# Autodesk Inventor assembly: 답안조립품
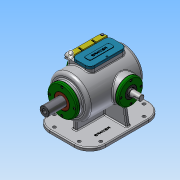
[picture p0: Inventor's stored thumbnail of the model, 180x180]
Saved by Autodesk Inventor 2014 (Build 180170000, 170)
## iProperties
Created: 2019-10
Part Number: 답안조립품
Document SubType Name: Assembly
Designer: net
Author: net
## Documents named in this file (17)
- C:\Users\net\Desktop\391004V1029\답안조립품.iam
- C:\Users\net\Desktop\391004V1029\본체.ipt
- C:\Users\net\Desktop\391004V1029\개스킷 A.ipt
- C:\Users\net\Desktop\391004V1029\개스킷 B.ipt
- C:\Users\net\Desktop\391004V1029\베어링 6205.ipt
- 베어링 6205.ipt
- C:\Users\net\Desktop\391004V1029\축 커버.ipt
- C:\Users\net\Desktop\391004V1029\오일 실 25 38 8.ipt
- C:\Users\net\Desktop\391004V1029\슬라이드 커버.ipt
- C:\Users\net\Desktop\391004V1029\부시.ipt
- C:\Users\net\Desktop\391004V1029\슬라이드.ipt
- C:\Users\net\Desktop\391004V1029\편심축.ipt
- C:\Users\net\Desktop\391004V1029\볼트 M4x0.7.ipt
- C:\Users\net\Desktop\391004V1029\상부커버.ipt
- C:\Users\net\Desktop\391004V1029\고정플레이트.ipt
- C:\Users\net\Desktop\391004V1029\육각머리볼트 M4.ipt
- C:\Users\net\Desktop\391004V1029\가변스프링.ipt
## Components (17 placed, 5 different names)
1. 개스킷 A:1
2. 개스킷 B:1
3. 개스킷 B:2
4. 고정플레이트:1 — 플러쉬:1
5. 가변스프링:1
6. M4x0.7:3
7. M4x0.7:4
8. M4x0.7:5
9. M4x0.7:6
10. M4x0.7:1
11. M4x0.7:7
12. M4x0.7:8
13. M4x0.7:9
14. M4x0.7:2
15. M4x0.7:10
16. M4x0.7:11
17. M4x0.7:12
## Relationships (1: Flush 1)
- 플러쉬:1 [Flush]: 고정플레이트:1
